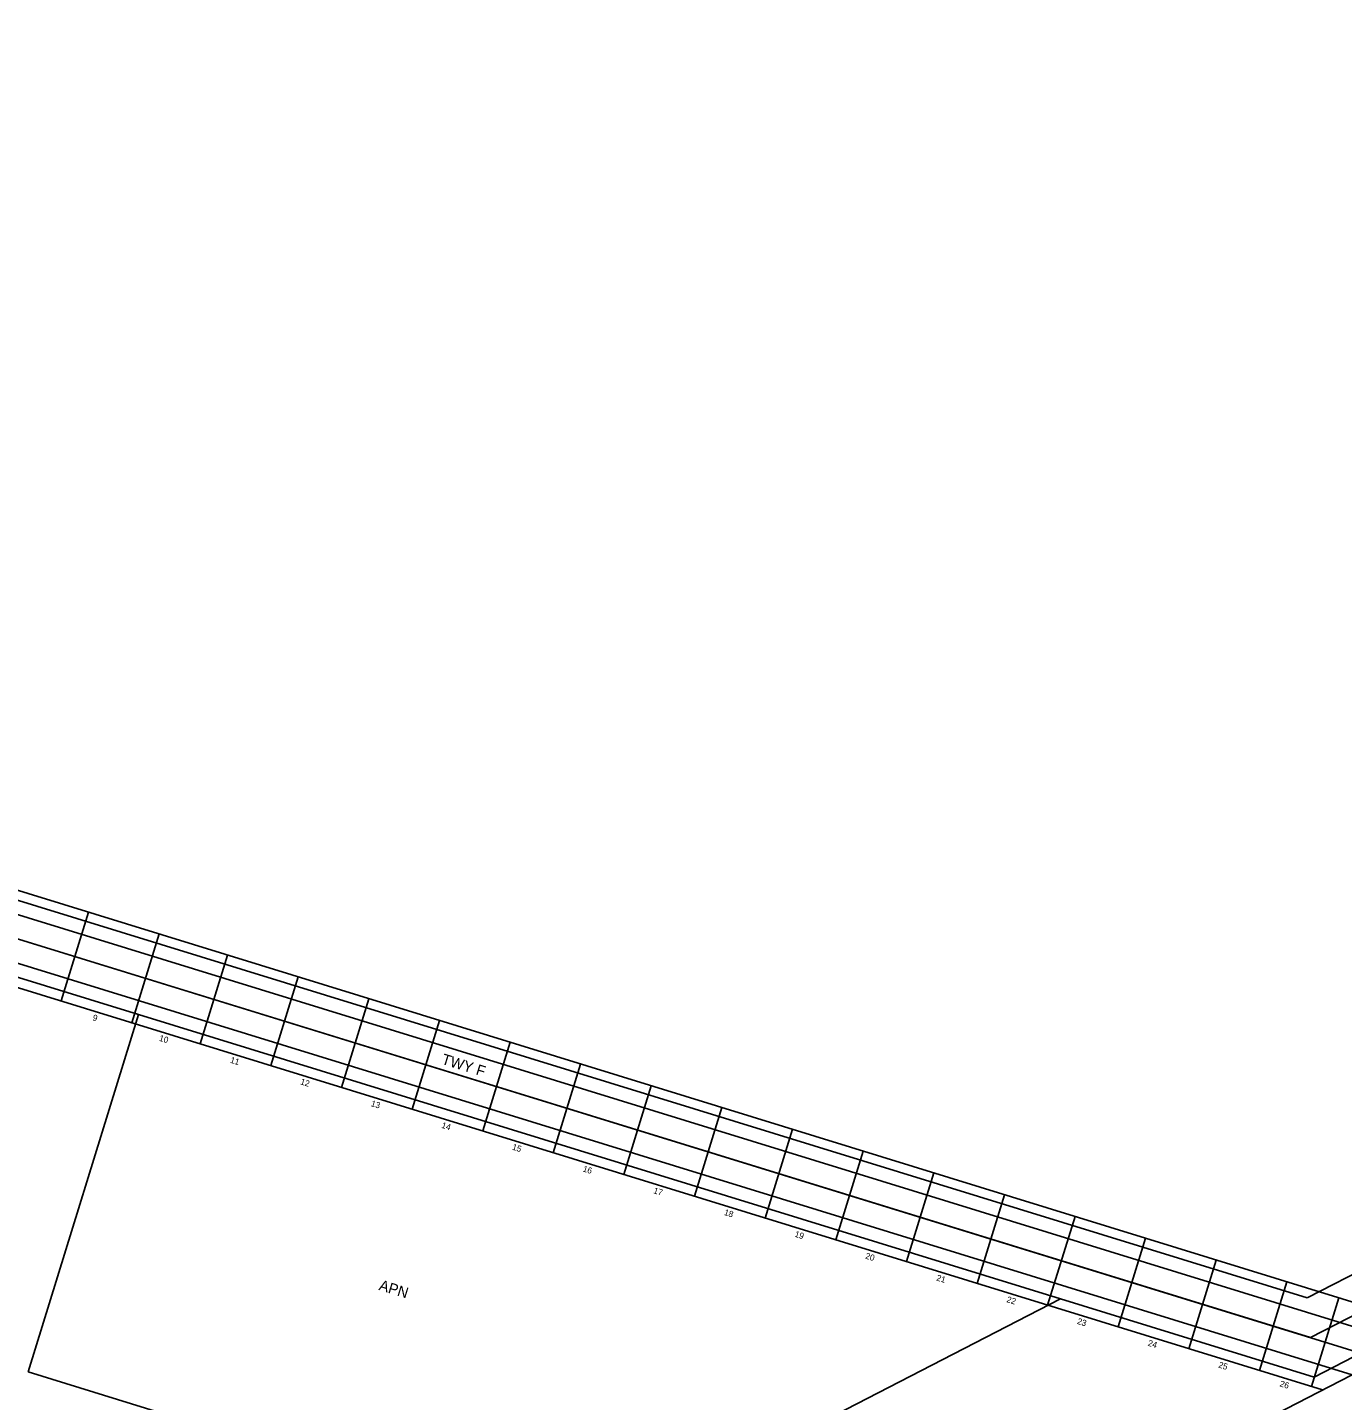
# Model space of a CAD drawing. Extents: x -886320 to -884760, y -1024172 to -1023483.
# Drawn here: x -886095.9 to -885881.5, y -1024051.4 to -1023827.5 of the extents above; entities that cross this region are included whole.
import ezdxf

# ---------------------------------------------------------------- set-up
doc = ezdxf.new("R2010")
doc.units = 0
for name, color, linetype in [('Stavajici_betonova_draha', 7, 'Continuous'), ('Stavajici_betonova_draha_Popis desky', 7, 'Continuous'), ('Stavajici_betonova_draha_Spára', 7, 'Continuous'), ('Stavajici_drahovy_system', 7, 'Continuous'), ('Stavajici_drahovy_system_popis', 7, 'Continuous'), ('Stavajici_drahovy_system_TWY', 7, 'Continuous'), ('Stavajici_drahovy_system_TWY_osy', 7, 'Continuous'), ('Stavajici_drahovy_system_TWY_popis', 7, 'Continuous')]:
    doc.layers.add(name, color=color, linetype=linetype)

msp = doc.modelspace()

# ---------------------------------------------------------------- linework, layer by layer
at = {"layer": 'Stavajici_betonova_draha'}
for p, q in [((-886029.69, -1024124.32), (-884785.04, -1023483.35)), ((-886029.69, -1024124.32), (-884785.04, -1023483.35)), ((-886315.74, -1023900.86), (-885865.51, -1024039.77)), ((-885884.75, -1024049.68), (-886320.21, -1023915.34))]:
    msp.add_line(p, q, dxfattribs=at)
at = {"layer": 'Stavajici_betonova_draha_Spára'}
for p, q in [((-886029.91, -1024124.43), (-884785.26, -1023483.46)), ((-885865.51, -1024039.77), (-886315.74, -1023900.86)), ((-885870.32, -1024042.24), (-886316.86, -1023904.48)), ((-885875.13, -1024044.72), (-886317.98, -1023908.1)), ((-885879.94, -1024047.2), (-886319.09, -1023911.72)), ((-885884.75, -1024049.68), (-886320.21, -1023915.34)), ((-886090.4, -1023986.23), (-886085.93, -1023971.76)), ((-886078.88, -1023989.79), (-886074.42, -1023975.31)), ((-886067.73, -1023993.23), (-886063.27, -1023978.75)), ((-886056.22, -1023996.78), (-886051.75, -1023982.31)), ((-886044.7, -1024000.33), (-886040.24, -1023985.86)), ((-886033.19, -1024003.88), (-886028.72, -1023989.41)), ((-886021.67, -1024007.43), (-886017.21, -1023992.96)), ((-886010.16, -1024010.99), (-886005.7, -1023996.52)), ((-885998.65, -1024014.54), (-885994.18, -1024000.07)), ((-885987.13, -1024018.09), (-885982.67, -1024003.62)), ((-885975.62, -1024021.64), (-885971.15, -1024007.17)), ((-885964.1, -1024025.2), (-885959.64, -1024010.73)), ((-885952.59, -1024028.75), (-885948.12, -1024014.28)), ((-885941.07, -1024032.3), (-885936.61, -1024017.83)), ((-885929.56, -1024035.85), (-885925.09, -1024021.38)), ((-885918.04, -1024039.41), (-885913.58, -1024024.93)), ((-885906.53, -1024042.96), (-885902.06, -1024028.49)), ((-885895.01, -1024046.51), (-885890.55, -1024032.04)), ((-885886.54, -1024049.13), (-885882.07, -1024034.65))]:
    msp.add_line(p, q, dxfattribs=at)
at = {"layer": 'Stavajici_drahovy_system'}
for p, q in [((-886095.78, -1024046.74), (-886077.8, -1023988.45)), ((-886005.01, -1024074.75), (-885927.49, -1024034.82)), ((-886095.78, -1024046.74), (-886005.01, -1024074.75))]:
    msp.add_line(p, q, dxfattribs=at)
at = {"layer": 'Stavajici_drahovy_system_TWY'}
for p, q in [((-885887.27, -1024034.67), (-884885.91, -1023518.99)), ((-885887.27, -1024034.67), (-886316.2, -1023902.35)), ((-886077.8, -1023988.45), (-886319.74, -1023913.81)), ((-885886.13, -1024047.58), (-885758.79, -1023982)), ((-885927.49, -1024034.82), (-886077.8, -1023988.45)), ((-885886.13, -1024047.58), (-885927.49, -1024034.82))]:
    msp.add_line(p, q, dxfattribs=at)
at = {"layer": 'Stavajici_drahovy_system_TWY_osy'}
for q in [(-884883.17, -1023524.32), (-886317.97, -1023908.08)]:
    msp.add_line((-885886.7, -1024041.13), q, dxfattribs=at)

# ---------------------------------------------------------------- texts
at = {"layer": 'Stavajici_betonova_draha_Popis desky'}
for s, p in [('9', (-886085.36, -1023989.36)), ('10', (-886074.51, -1023992.7)), ('11', (-886062.92, -1023996.28)), ('12', (-886051.48, -1023999.81)), ('13', (-886039.97, -1024003.36)), ('14', (-886028.46, -1024006.91)), ('15', (-886016.95, -1024010.46)), ('16', (-886005.43, -1024014.02)), ('17', (-885993.91, -1024017.57)), ('18', (-885982.4, -1024021.12)), ('19', (-885970.89, -1024024.67)), ('20', (-885959.37, -1024028.23)), ('21', (-885947.78, -1024031.8)), ('22', (-885936.34, -1024035.33)), ('23', (-885924.83, -1024038.88)), ('24', (-885913.31, -1024042.44)), ('25', (-885901.8, -1024045.99)), ('26', (-885891.8, -1024049.07))]:
    msp.add_text(s, height=1, rotation=342.8547, dxfattribs=at).set_placement(p)
at = {"layer": 'Stavajici_drahovy_system_popis'}
msp.add_text('APN', height=1.75, rotation=342.8547, dxfattribs=at).set_placement((-886038.71, -1024033.34))
at = {"layer": 'Stavajici_drahovy_system_TWY_popis'}
msp.add_text('TWY F', height=1.75, rotation=342.8547, dxfattribs=at).set_placement((-886028.49, -1023996.47))

doc.saveas('drawing.dxf')
